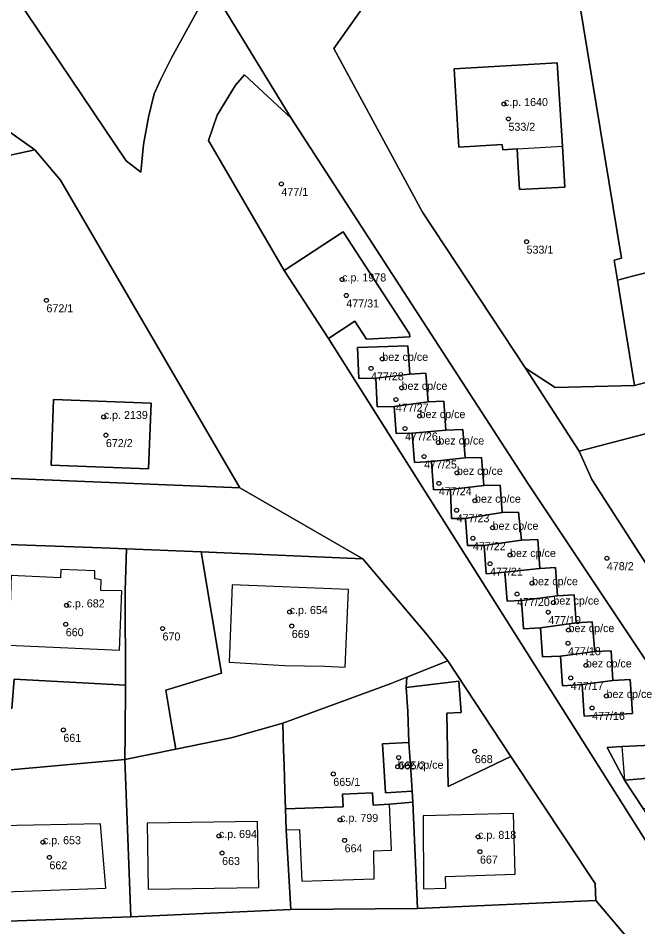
# Model space of a CAD drawing. Extents: x -878211 to -870363, y -1058464 to -1052522.
# Drawn here: x -874398.3 to -874320.9, y -1056539.1 to -1056425.6 of the extents above; entities that cross this region are included whole.
import ezdxf

# ---------------------------------------------------------------- set-up
doc = ezdxf.new("R2010")
doc.units = 0
for name, color, linetype in [('Vrstva 50', 7, 'Continuous'), ('Vrstva 51', 7, 'Continuous'), ('Vrstva 52', 7, 'Continuous')]:
    doc.layers.add(name, color=color, linetype=linetype)

msp = doc.modelspace()

# ---------------------------------------------------------------- linework, layer by layer
at = {"layer": 'Vrstva 50'}
for centre in [(-874337.61, -1056436.31994), (-874337.04, -1056438.16994), (-874365.39, -1056446.29994), (-874334.78, -1056453.51994), (-874357.81, -1056458.23994), (-874394.73, -1056460.84994), (-874357.29, -1056460.23994), (-874352.79, -1056468.15994), (-874354.2, -1056469.34994), (-874350.39, -1056471.77994), (-874351.1, -1056473.24994), (-874387.58, -1056475.41994), (-874348.14, -1056475.30994), (-874387.31, -1056477.68994), (-874349.95, -1056476.85994), (-874345.79, -1056478.60994), (-874347.57, -1056480.35994), (-874343.47, -1056482.39994), (-874345.73, -1056483.70994), (-874341.22, -1056485.87994), (-874343.51, -1056487.07994), (-874339.02, -1056489.25994), (-874341.48, -1056490.57994), (-874339.34, -1056493.75994), (-874336.84, -1056492.66994), (-874324.75, -1056493.06994), (-874334.09, -1056496.18994), (-874335.97, -1056497.54994), (-874392.22, -1056498.95994), (-874331.43, -1056498.60994), (-874364.36, -1056499.78994), (-874332.07, -1056499.80994), (-874392.32, -1056501.31994), (-874364.1, -1056501.53994), (-874380.24, -1056501.84994), (-874329.54, -1056502.04994), (-874329.6, -1056503.68994), (-874327.37, -1056506.45994), (-874329.26, -1056508.02994), (-874324.8, -1056510.27994), (-874326.59, -1056511.76994), (-874392.62, -1056514.51994), (-874341.24, -1056517.17994), (-874350.76, -1056517.96994), (-874350.87, -1056519.11994), (-874358.91, -1056520.01994), (-874358.06, -1056525.75994), (-874373.2, -1056527.76994), (-874395.18, -1056528.54994), (-874357.5, -1056528.31994), (-874340.83, -1056527.87994), (-874372.8, -1056529.90994), (-874340.6, -1056529.72994), (-874394.36, -1056530.43994)]:
    msp.add_circle(centre, 0.25, dxfattribs=at)
at = {"layer": 'Vrstva 51'}
for points in [[(-874435.23, -1056399.98), (-874420.12, -1056431.27), (-874417.67, -1056433.88), (-874411.69, -1056441.25), (-874402.98, -1056437.26), (-874396.18, -1056442.04), (-874393, -1056445.85), (-874370.58, -1056484.27), (-874355.24, -1056493.16), (-874347.2, -1056502.65), (-874344.62, -1056505.87), (-874336.73, -1056517.84), (-874326.2, -1056533.69), (-874326.13, -1056535.82), (-874319.45, -1056543.71), (-874311.18, -1056556.62)], [(-874375.26, -1056423.52), (-874379.13, -1056430.54), (-874380.43, -1056433.22), (-874381.27, -1056435.06), (-874382, -1056437.94), (-874382.6, -1056441.37), (-874382.93, -1056444.85), (-874384.79, -1056443.42), (-874399.99, -1056420.8)], [(-874359.52, -1056465.6), (-874365.05, -1056457.11), (-874374.51, -1056440.86), (-874373.43, -1056437.7), (-874371.12, -1056433.98), (-874370.01, -1056432.66), (-874364.19, -1056438.09), (-874374.27, -1056421.51)], [(-874374.27, -1056421.51), (-874364.19, -1056438.09), (-874334.57, -1056483.76), (-874308.37, -1056523.13), (-874269.31, -1056582.53)], [(-874274.54, -1056564.3), (-874281.34, -1056555.14), (-874302.81, -1056520.2), (-874326.64, -1056483.24), (-874328.23, -1056479.69), (-874334.9, -1056469.3), (-874347.77, -1056449.81), (-874358.83, -1056429.38), (-874355.4, -1056424.52)], [(-874269.31, -1056582.53), (-874308.37, -1056523.13), (-874334.57, -1056483.76), (-874364.19, -1056438.09), (-874370.01, -1056432.66), (-874371.12, -1056433.98), (-874373.43, -1056437.7), (-874374.51, -1056440.86), (-874365.05, -1056457.11), (-874357.66, -1056452.3), (-874349.38, -1056465.01), (-874349.37, -1056465.41), (-874354.76, -1056465.71), (-874356.24, -1056463.46), (-874359.52, -1056465.6), (-874291.5, -1056573.37), (-874282.53, -1056587.29), (-874281.7, -1056588.08), (-874280.88, -1056588.76), (-874279.96, -1056589.37), (-874279, -1056589.96), (-874278.23, -1056590.45)], [(-874273.03, -1056462.79), (-874285.05, -1056464.33), (-874292.09, -1056465.18), (-874299.71, -1056465.83), (-874304.96, -1056466.94), (-874311.94, -1056468.99), (-874321.3, -1056471.47), (-874331.21, -1056471.74), (-874334.9, -1056469.3), (-874328.23, -1056479.69), (-874313.25, -1056475.76), (-874296.79, -1056472.76), (-874276.36, -1056470.37)], [(-874278.23, -1056590.45), (-874279, -1056589.96), (-874279.96, -1056589.37), (-874280.88, -1056588.76), (-874281.7, -1056588.08), (-874282.53, -1056587.29), (-874291.5, -1056573.37), (-874359.52, -1056465.6)], [(-874400.72, -1056491.29), (-874387.81, -1056491.77), (-874384.75, -1056491.88), (-874375.43, -1056492.28), (-874355.24, -1056493.16), (-874370.58, -1056484.27), (-874404.23, -1056482.9)], [(-874308.51, -1056541.53), (-874310.84, -1056538.07), (-874313.21, -1056534.69), (-874315.55, -1056531.25), (-874317.92, -1056527.83), (-874320.23, -1056524.33), (-874322.55, -1056520.79), (-874324.72, -1056516.73), (-874322.88, -1056516.61), (-874316.48, -1056516.31), (-874316.13, -1056520.09), (-874314.15, -1056519.95), (-874313.86, -1056523.55), (-874311.88, -1056523.38), (-874311.58, -1056526.99), (-874309.58, -1056526.83), (-874309.25, -1056530.44), (-874307.25, -1056530.29), (-874306.9, -1056533.88), (-874304.88, -1056533.75), (-874304.61, -1056537.26), (-874302.55, -1056537.15), (-874302.23, -1056540.78)]]:
    msp.add_lwpolyline(points, dxfattribs=at)
for points in [[(-874413.76, -1056402.45), (-874399.99, -1056420.8), (-874384.79, -1056443.42), (-874382.93, -1056444.85), (-874382.6, -1056441.37), (-874382, -1056437.94), (-874381.27, -1056435.06), (-874380.43, -1056433.22), (-874379.13, -1056430.54), (-874375.26, -1056423.52), (-874374.27, -1056421.51), (-874373, -1056417.98), (-874372.17, -1056413.82), (-874372.03, -1056411.06), (-874380.96, -1056409.78), (-874388.01, -1056408.78), (-874394.12, -1056407.72), (-874399.07, -1056406.68)], [(-874307.26, -1056421.69), (-874328.21, -1056423.41), (-874322.92, -1056455.59), (-874323.82, -1056455.82), (-874323.42, -1056458.31), (-874321.4, -1056457.79), (-874316.56, -1056456.56), (-874301.92, -1056452.52)], [(-874322.92, -1056455.59), (-874328.21, -1056423.41), (-874355.4, -1056424.52), (-874358.83, -1056429.38), (-874347.77, -1056449.81), (-874334.9, -1056469.3), (-874331.21, -1056471.74), (-874321.3, -1056471.47), (-874323.42, -1056458.31), (-874323.82, -1056455.82)], [(-874417.41, -1056446.4), (-874407.71, -1056444.55), (-874396.18, -1056442.04), (-874402.98, -1056437.26), (-874411.69, -1056441.25), (-874417.67, -1056433.88), (-874420.12, -1056431.27), (-874425.29, -1056433.14), (-874426.38, -1056448.38)], [(-874330.31, -1056441.6), (-874329.99, -1056446.69), (-874335.66, -1056447.01), (-874335.87, -1056443.53), (-874335.97, -1056441.92), (-874337.75, -1056442.02), (-874337.82, -1056441.38), (-874343.22, -1056441.71), (-874343.81, -1056431.94), (-874330.97, -1056431.19)], [(-874330.31, -1056441.6), (-874330.97, -1056431.19), (-874343.81, -1056431.94), (-874343.22, -1056441.71), (-874337.82, -1056441.38), (-874337.75, -1056442.02), (-874335.97, -1056441.92), (-874335.87, -1056443.53), (-874335.66, -1056447.01), (-874329.99, -1056446.69)], [(-874404.47, -1056480.3), (-874404.23, -1056482.9), (-874370.58, -1056484.27), (-874393, -1056445.85), (-874396.18, -1056442.04), (-874407.71, -1056444.55), (-874405.42, -1056469.74)], [(-874365.05, -1056457.11), (-874359.52, -1056465.6), (-874356.24, -1056463.46), (-874354.76, -1056465.71), (-874349.37, -1056465.41), (-874349.38, -1056465.01), (-874357.66, -1056452.3)], [(-874321.4, -1056457.79), (-874323.42, -1056458.31), (-874321.3, -1056471.47), (-874311.94, -1056468.99), (-874304.96, -1056466.94), (-874299.71, -1056465.83), (-874301.92, -1056452.52), (-874316.56, -1056456.56)], [(-874349.36, -1056470.06), (-874349.6, -1056466.51), (-874355.91, -1056466.74), (-874355.73, -1056470.61), (-874353.59, -1056470.55)], [(-874349.36, -1056470.06), (-874347.35, -1056469.95), (-874347.07, -1056473.52), (-874345.13, -1056473.46), (-874344.88, -1056477.06), (-874342.73, -1056477), (-874342.44, -1056480.51), (-874340.42, -1056480.48), (-874340.12, -1056483.96), (-874338.08, -1056483.93), (-874337.84, -1056487.36), (-874335.77, -1056487.3), (-874335.4, -1056490.83), (-874333.37, -1056490.71), (-874333.11, -1056494.33), (-874331.15, -1056494.21), (-874330.92, -1056497.75), (-874328.83, -1056497.65), (-874328.58, -1056501.15), (-874326.58, -1056501), (-874326.26, -1056504.73), (-874324.22, -1056504.62), (-874324.01, -1056508.35), (-874321.85, -1056508.22), (-874321.55, -1056512.45), (-874327.57, -1056512.82), (-874327.84, -1056508.85), (-874330.27, -1056509.03), (-874330.52, -1056505.29), (-874332.77, -1056505.4), (-874333.05, -1056501.76), (-874335.17, -1056501.88), (-874335.41, -1056498.33), (-874337.22, -1056498.43), (-874337.49, -1056494.8), (-874339.84, -1056495.02), (-874340.07, -1056491.47), (-874342.16, -1056491.49), (-874342.42, -1056488.11), (-874344.15, -1056488.12), (-874344.29, -1056484.47), (-874346.38, -1056484.54), (-874346.67, -1056481), (-874348.76, -1056481.09), (-874349.06, -1056477.45), (-874351.08, -1056477.49), (-874351.32, -1056474.09), (-874353.43, -1056474.15), (-874353.59, -1056470.55), (-874355.73, -1056470.61), (-874355.91, -1056466.74), (-874349.6, -1056466.51)], [(-874353.59, -1056470.55), (-874353.43, -1056474.15), (-874351.32, -1056474.09), (-874347.07, -1056473.52), (-874347.35, -1056469.95), (-874349.36, -1056470.06)], [(-874297.52, -1056492.1), (-874298.81, -1056486.15), (-874294.43, -1056485.09), (-874296.79, -1056472.76), (-874313.25, -1056475.76), (-874328.23, -1056479.69), (-874326.64, -1056483.24), (-874302.81, -1056520.2), (-874288.39, -1056517.65), (-874293.11, -1056491)], [(-874394.16, -1056481.43), (-874393.85, -1056473.25), (-874381.67, -1056473.7), (-874381.97, -1056481.9)], [(-874394.16, -1056481.43), (-874381.97, -1056481.9), (-874381.67, -1056473.7), (-874393.85, -1056473.25)], [(-874347.07, -1056473.52), (-874351.32, -1056474.09), (-874351.08, -1056477.49), (-874349.06, -1056477.45), (-874344.88, -1056477.06), (-874345.13, -1056473.46)], [(-874349.06, -1056477.45), (-874348.76, -1056481.09), (-874346.67, -1056481), (-874342.44, -1056480.51), (-874342.73, -1056477), (-874344.88, -1056477.06)], [(-874342.44, -1056480.51), (-874346.67, -1056481), (-874346.38, -1056484.54), (-874344.29, -1056484.47), (-874340.12, -1056483.96), (-874340.42, -1056480.48)], [(-874340.12, -1056483.96), (-874344.29, -1056484.47), (-874344.15, -1056488.12), (-874342.42, -1056488.11), (-874337.84, -1056487.36), (-874338.08, -1056483.93)], [(-874337.84, -1056487.36), (-874342.42, -1056488.11), (-874342.16, -1056491.49), (-874340.07, -1056491.47), (-874335.4, -1056490.83), (-874335.77, -1056487.3)], [(-874335.4, -1056490.83), (-874340.07, -1056491.47), (-874339.84, -1056495.02), (-874337.49, -1056494.8), (-874333.11, -1056494.33), (-874333.37, -1056490.71)], [(-874384.75, -1056491.88), (-874387.81, -1056491.77), (-874400.72, -1056491.29), (-874401.15, -1056504.66), (-874401.29, -1056510.7), (-874401.27, -1056511.78), (-874399.06, -1056511.86), (-874398.75, -1056508.19), (-874384.85, -1056508.94), (-874384.89, -1056497.15)], [(-874375.43, -1056492.28), (-874384.75, -1056491.88), (-874384.89, -1056497.15), (-874384.85, -1056508.94), (-874384.91, -1056515.08), (-874384.94, -1056518.23), (-874378.57, -1056516.92), (-874379.07, -1056514.03), (-874379.84, -1056509.55), (-874372.88, -1056507.41)], [(-874355.24, -1056493.16), (-874375.43, -1056492.28), (-874372.88, -1056507.41), (-874379.84, -1056509.55), (-874379.07, -1056514.03), (-874378.57, -1056516.92), (-874371.65, -1056515.5), (-874365.23, -1056513.68), (-874351.82, -1056508.78), (-874349.72, -1056507.92), (-874344.62, -1056505.87), (-874347.2, -1056502.65)], [(-874333.11, -1056494.33), (-874337.49, -1056494.8), (-874337.22, -1056498.43), (-874335.41, -1056498.33), (-874330.92, -1056497.75), (-874331.15, -1056494.21)], [(-874335.41, -1056498.33), (-874335.17, -1056501.88), (-874333.05, -1056501.76), (-874328.58, -1056501.15), (-874328.83, -1056497.65), (-874330.92, -1056497.75)], [(-874328.58, -1056501.15), (-874333.05, -1056501.76), (-874332.77, -1056505.4), (-874330.52, -1056505.29), (-874326.26, -1056504.73), (-874326.58, -1056501)], [(-874326.26, -1056504.73), (-874330.52, -1056505.29), (-874330.27, -1056509.03), (-874327.84, -1056508.85), (-874324.01, -1056508.35), (-874324.22, -1056504.62)], [(-874349.72, -1056507.92), (-874349.83, -1056509.2), (-874343.24, -1056508.41), (-874342.96, -1056512.33), (-874344.72, -1056512.44), (-874344.55, -1056521.6), (-874336.73, -1056517.84), (-874344.62, -1056505.87)], [(-874384.94, -1056518.23), (-874384.91, -1056515.08), (-874384.85, -1056508.94), (-874398.75, -1056508.19), (-874399.06, -1056511.86), (-874401.27, -1056511.78), (-874401.52, -1056519.71), (-874400.62, -1056519.62)], [(-874349.83, -1056509.2), (-874349.72, -1056507.92), (-874351.82, -1056508.78), (-874365.23, -1056513.68), (-874365.12, -1056517.01), (-874365.06, -1056518.93), (-874364.95, -1056522.08), (-874364.87, -1056524.37), (-874357.7, -1056524.11), (-874357.76, -1056522.56), (-874354.02, -1056522.39), (-874353.93, -1056523.92), (-874351.91, -1056523.79), (-874348.98, -1056523.53), (-874349.06, -1056522.17), (-874352.39, -1056522.37), (-874352.78, -1056516.27), (-874349.47, -1056516.11), (-874349.61, -1056512.23)], [(-874324.01, -1056508.35), (-874327.84, -1056508.85), (-874327.57, -1056512.82), (-874321.55, -1056512.45), (-874321.85, -1056508.22)], [(-874343.24, -1056508.41), (-874349.83, -1056509.2), (-874349.61, -1056512.23), (-874349.47, -1056516.11), (-874349.19, -1056520.18), (-874349.06, -1056522.17), (-874348.98, -1056523.53), (-874348.38, -1056536.81), (-874326.13, -1056535.82), (-874326.2, -1056533.69), (-874336.73, -1056517.84), (-874344.55, -1056521.6), (-874344.72, -1056512.44), (-874342.96, -1056512.33)], [(-874365.12, -1056517.01), (-874365.23, -1056513.68), (-874371.65, -1056515.5), (-874378.57, -1056516.92), (-874384.94, -1056518.23), (-874384.19, -1056537.86), (-874364.21, -1056536.96), (-874364.78, -1056527.01), (-874364.87, -1056524.37), (-874364.95, -1056522.08), (-874365.06, -1056518.93)], [(-874349.19, -1056520.18), (-874349.47, -1056516.11), (-874352.78, -1056516.27), (-874352.39, -1056522.37), (-874349.06, -1056522.17)], [(-874316.13, -1056520.09), (-874316.48, -1056516.31), (-874322.88, -1056516.61), (-874324.72, -1056516.73), (-874322.55, -1056520.79), (-874320.47, -1056520.64)], [(-874384.94, -1056518.23), (-874400.62, -1056519.62), (-874401.52, -1056519.71), (-874404.16, -1056519.98), (-874403.81, -1056526.63), (-874403.37, -1056534.89), (-874403.14, -1056538.55), (-874384.19, -1056537.86)], [(-874320.47, -1056520.64), (-874322.55, -1056520.79), (-874320.23, -1056524.33), (-874318.35, -1056524.2), (-874318.35, -1056523.91), (-874313.86, -1056523.55), (-874314.15, -1056519.95), (-874316.13, -1056520.09)], [(-874353.93, -1056523.92), (-874354.02, -1056522.39), (-874357.76, -1056522.56), (-874357.7, -1056524.11), (-874364.87, -1056524.37), (-874364.78, -1056527.01), (-874364.21, -1056536.96), (-874348.38, -1056536.81), (-874348.98, -1056523.53), (-874351.91, -1056523.79)], [(-874330.78, -1056544.15), (-874321.63, -1056543.78), (-874319.45, -1056543.71), (-874326.13, -1056535.82), (-874348.38, -1056536.81), (-874364.21, -1056536.96), (-874384.19, -1056537.86), (-874403.14, -1056538.55), (-874419.92, -1056539.28), (-874440.04, -1056540.15), (-874428.62, -1056547.76), (-874417.19, -1056547.36), (-874405.53, -1056546.89), (-874402.16, -1056546.76), (-874383.9, -1056546.09), (-874373.1, -1056545.73), (-874365.49, -1056545.45), (-874362.2, -1056545.35), (-874355.93, -1056545.07), (-874349.64, -1056544.84), (-874344.53, -1056544.62), (-874343.6, -1056544.63), (-874336.58, -1056544.39), (-874332.88, -1056544.22)]]:
    msp.add_lwpolyline(points, close=True, dxfattribs=at)
at = {"layer": 'Vrstva 52'}
for points in [[(-874343.81, -1056431.94), (-874343.22, -1056441.71), (-874337.82, -1056441.38), (-874337.75, -1056442.02), (-874335.97, -1056441.92), (-874330.31, -1056441.6), (-874330.97, -1056431.19)], [(-874365.05, -1056457.11), (-874359.52, -1056465.6), (-874356.24, -1056463.46), (-874354.76, -1056465.71), (-874349.37, -1056465.41), (-874349.38, -1056465.01), (-874357.66, -1056452.3)], [(-874355.91, -1056466.74), (-874355.73, -1056470.61), (-874353.59, -1056470.55), (-874349.36, -1056470.06), (-874349.6, -1056466.51)], [(-874349.36, -1056470.06), (-874353.59, -1056470.55), (-874353.43, -1056474.15), (-874351.32, -1056474.09), (-874347.07, -1056473.52), (-874347.35, -1056469.95)], [(-874394.16, -1056481.43), (-874381.97, -1056481.9), (-874381.67, -1056473.7), (-874393.85, -1056473.25)], [(-874351.32, -1056474.09), (-874351.08, -1056477.49), (-874349.06, -1056477.45), (-874344.88, -1056477.06), (-874345.13, -1056473.46), (-874347.07, -1056473.52)], [(-874344.88, -1056477.06), (-874349.06, -1056477.45), (-874348.76, -1056481.09), (-874346.67, -1056481), (-874342.44, -1056480.51), (-874342.73, -1056477)], [(-874346.67, -1056481), (-874346.38, -1056484.54), (-874344.29, -1056484.47), (-874340.12, -1056483.96), (-874340.42, -1056480.48), (-874342.44, -1056480.51)], [(-874337.84, -1056487.36), (-874338.08, -1056483.93), (-874340.12, -1056483.96), (-874344.29, -1056484.47), (-874344.15, -1056488.12), (-874342.42, -1056488.11)], [(-874342.42, -1056488.11), (-874342.16, -1056491.49), (-874340.07, -1056491.47), (-874335.4, -1056490.83), (-874335.77, -1056487.3), (-874337.84, -1056487.36)], [(-874340.07, -1056491.47), (-874339.84, -1056495.02), (-874337.49, -1056494.8), (-874333.11, -1056494.33), (-874333.37, -1056490.71), (-874335.4, -1056490.83)], [(-874399.45, -1056503.94), (-874385.6, -1056504.57), (-874385.3, -1056497.14), (-874387.93, -1056497.08), (-874387.9, -1056495.77), (-874388.71, -1056495.65), (-874388.7, -1056494.66), (-874392.94, -1056494.48), (-874393, -1056495.51), (-874399.12, -1056495.24)], [(-874337.49, -1056494.8), (-874337.22, -1056498.43), (-874335.41, -1056498.33), (-874330.92, -1056497.75), (-874331.15, -1056494.21), (-874333.11, -1056494.33)], [(-874371.91, -1056506.07), (-874365.02, -1056506.46), (-874360.02, -1056506.56), (-874357.43, -1056506.69), (-874357.03, -1056496.98), (-874371.54, -1056496.4)], [(-874335.41, -1056498.33), (-874335.17, -1056501.88), (-874333.05, -1056501.76), (-874328.58, -1056501.15), (-874328.83, -1056497.65), (-874330.92, -1056497.75)], [(-874333.05, -1056501.76), (-874332.77, -1056505.4), (-874330.52, -1056505.29), (-874326.26, -1056504.73), (-874326.58, -1056501), (-874328.58, -1056501.15)], [(-874330.52, -1056505.29), (-874330.27, -1056509.03), (-874327.84, -1056508.85), (-874324.01, -1056508.35), (-874324.22, -1056504.62), (-874326.26, -1056504.73)], [(-874327.84, -1056508.85), (-874327.57, -1056512.82), (-874321.55, -1056512.45), (-874321.85, -1056508.22), (-874324.01, -1056508.35)], [(-874349.47, -1056516.11), (-874352.78, -1056516.27), (-874352.39, -1056522.37), (-874349.06, -1056522.17), (-874349.19, -1056520.18)], [(-874322.88, -1056516.61), (-874322.55, -1056520.79), (-874320.47, -1056520.64), (-874316.13, -1056520.09), (-874316.48, -1056516.31)], [(-874354.02, -1056522.39), (-874357.76, -1056522.56), (-874357.7, -1056524.11), (-874364.87, -1056524.37), (-874364.78, -1056527.01), (-874363.12, -1056526.95), (-874362.86, -1056533.43), (-874353.79, -1056533.11), (-874353.87, -1056529.63), (-874351.66, -1056529.56), (-874351.91, -1056523.79), (-874353.93, -1056523.92)], [(-874347.7, -1056525.27), (-874347.64, -1056534.37), (-874344.87, -1056534.3), (-874344.89, -1056532.85), (-874336.22, -1056532.56), (-874336.4, -1056524.96)], [(-874400.54, -1056526.5), (-874403.81, -1056526.63), (-874403.37, -1056534.89), (-874387.3, -1056534.3), (-874387.99, -1056526.27)], [(-874382.14, -1056526.18), (-874382.02, -1056534.41), (-874368.22, -1056534.2), (-874368.38, -1056525.97)]]:
    msp.add_lwpolyline(points, close=True, dxfattribs=at)

# ---------------------------------------------------------------- texts
at = {"layer": 'Vrstva 50'}
for s, p in [('c.p. 1640', (-874337.61, -1056436.57)), ('533/2', (-874337.04, -1056439.659)), ('477/1', (-874365.39, -1056447.789)), ('533/1', (-874334.78, -1056455.009)), ('c.p. 1978', (-874357.81, -1056458.49)), ('672/1', (-874394.73, -1056462.339)), ('477/31', (-874357.29, -1056461.729)), ('bez cp/ce', (-874352.79, -1056468.409)), ('477/28', (-874354.2, -1056470.839)), ('bez cp/ce', (-874350.39, -1056472.03)), ('477/27', (-874351.1, -1056474.739)), ('c.p. 2139', (-874387.58, -1056475.669)), ('bez cp/ce', (-874348.14, -1056475.56)), ('477/26', (-874349.95, -1056478.349)), ('672/2', (-874387.31, -1056479.179)), ('bez cp/ce', (-874345.79, -1056478.86)), ('477/25', (-874347.57, -1056481.849)), ('bez cp/ce', (-874343.47, -1056482.649)), ('477/24', (-874345.73, -1056485.199)), ('bez cp/ce', (-874341.22, -1056486.129)), ('477/23', (-874343.51, -1056488.569)), ('bez cp/ce', (-874339.02, -1056489.51)), ('477/22', (-874341.48, -1056492.069)), ('bez cp/ce', (-874336.84, -1056492.919)), ('478/2', (-874324.75, -1056494.559)), ('477/21', (-874339.34, -1056495.249)), ('bez cp/ce', (-874334.09, -1056496.44)), ('477/20', (-874335.97, -1056499.039)), ('bez cp/ce', (-874331.43, -1056498.86)), ('c.p. 682', (-874392.22, -1056499.21)), ('c.p. 654', (-874364.36, -1056500.04)), ('477/19', (-874332.07, -1056501.299)), ('bez cp/ce', (-874329.54, -1056502.3)), ('660', (-874392.32, -1056502.809)), ('670', (-874380.24, -1056503.339)), ('669', (-874364.1, -1056503.029)), ('477/18', (-874329.6, -1056505.179)), ('bez cp/ce', (-874327.37, -1056506.71)), ('477/17', (-874329.26, -1056509.519)), ('bez cp/ce', (-874324.8, -1056510.53)), ('477/16', (-874326.59, -1056513.259)), ('661', (-874392.62, -1056516.009)), ('bez cp/ce', (-874350.87, -1056519.37)), ('665/2', (-874350.76, -1056519.459)), ('668', (-874341.24, -1056518.669)), ('665/1', (-874358.91, -1056521.509)), ('c.p. 799', (-874358.06, -1056526.01)), ('c.p. 694', (-874373.2, -1056528.02)), ('c.p. 818', (-874340.83, -1056528.129)), ('c.p. 653', (-874395.18, -1056528.8)), ('664', (-874357.5, -1056529.809)), ('662', (-874394.36, -1056531.929)), ('663', (-874372.8, -1056531.399)), ('667', (-874340.6, -1056531.219))]:
    msp.add_text(s, height=0.999996, dxfattribs=at).set_placement(p)

doc.saveas('drawing.dxf')
